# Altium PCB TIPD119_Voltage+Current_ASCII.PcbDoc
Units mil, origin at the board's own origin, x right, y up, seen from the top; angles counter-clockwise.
Board outline 2500 x 2500 mil, 4 copper layers (Top Layer, Mid-Layer 1, Mid-Layer 2, Bottom Layer); 44 components, 24 nets, 146 pads, 95 vias.
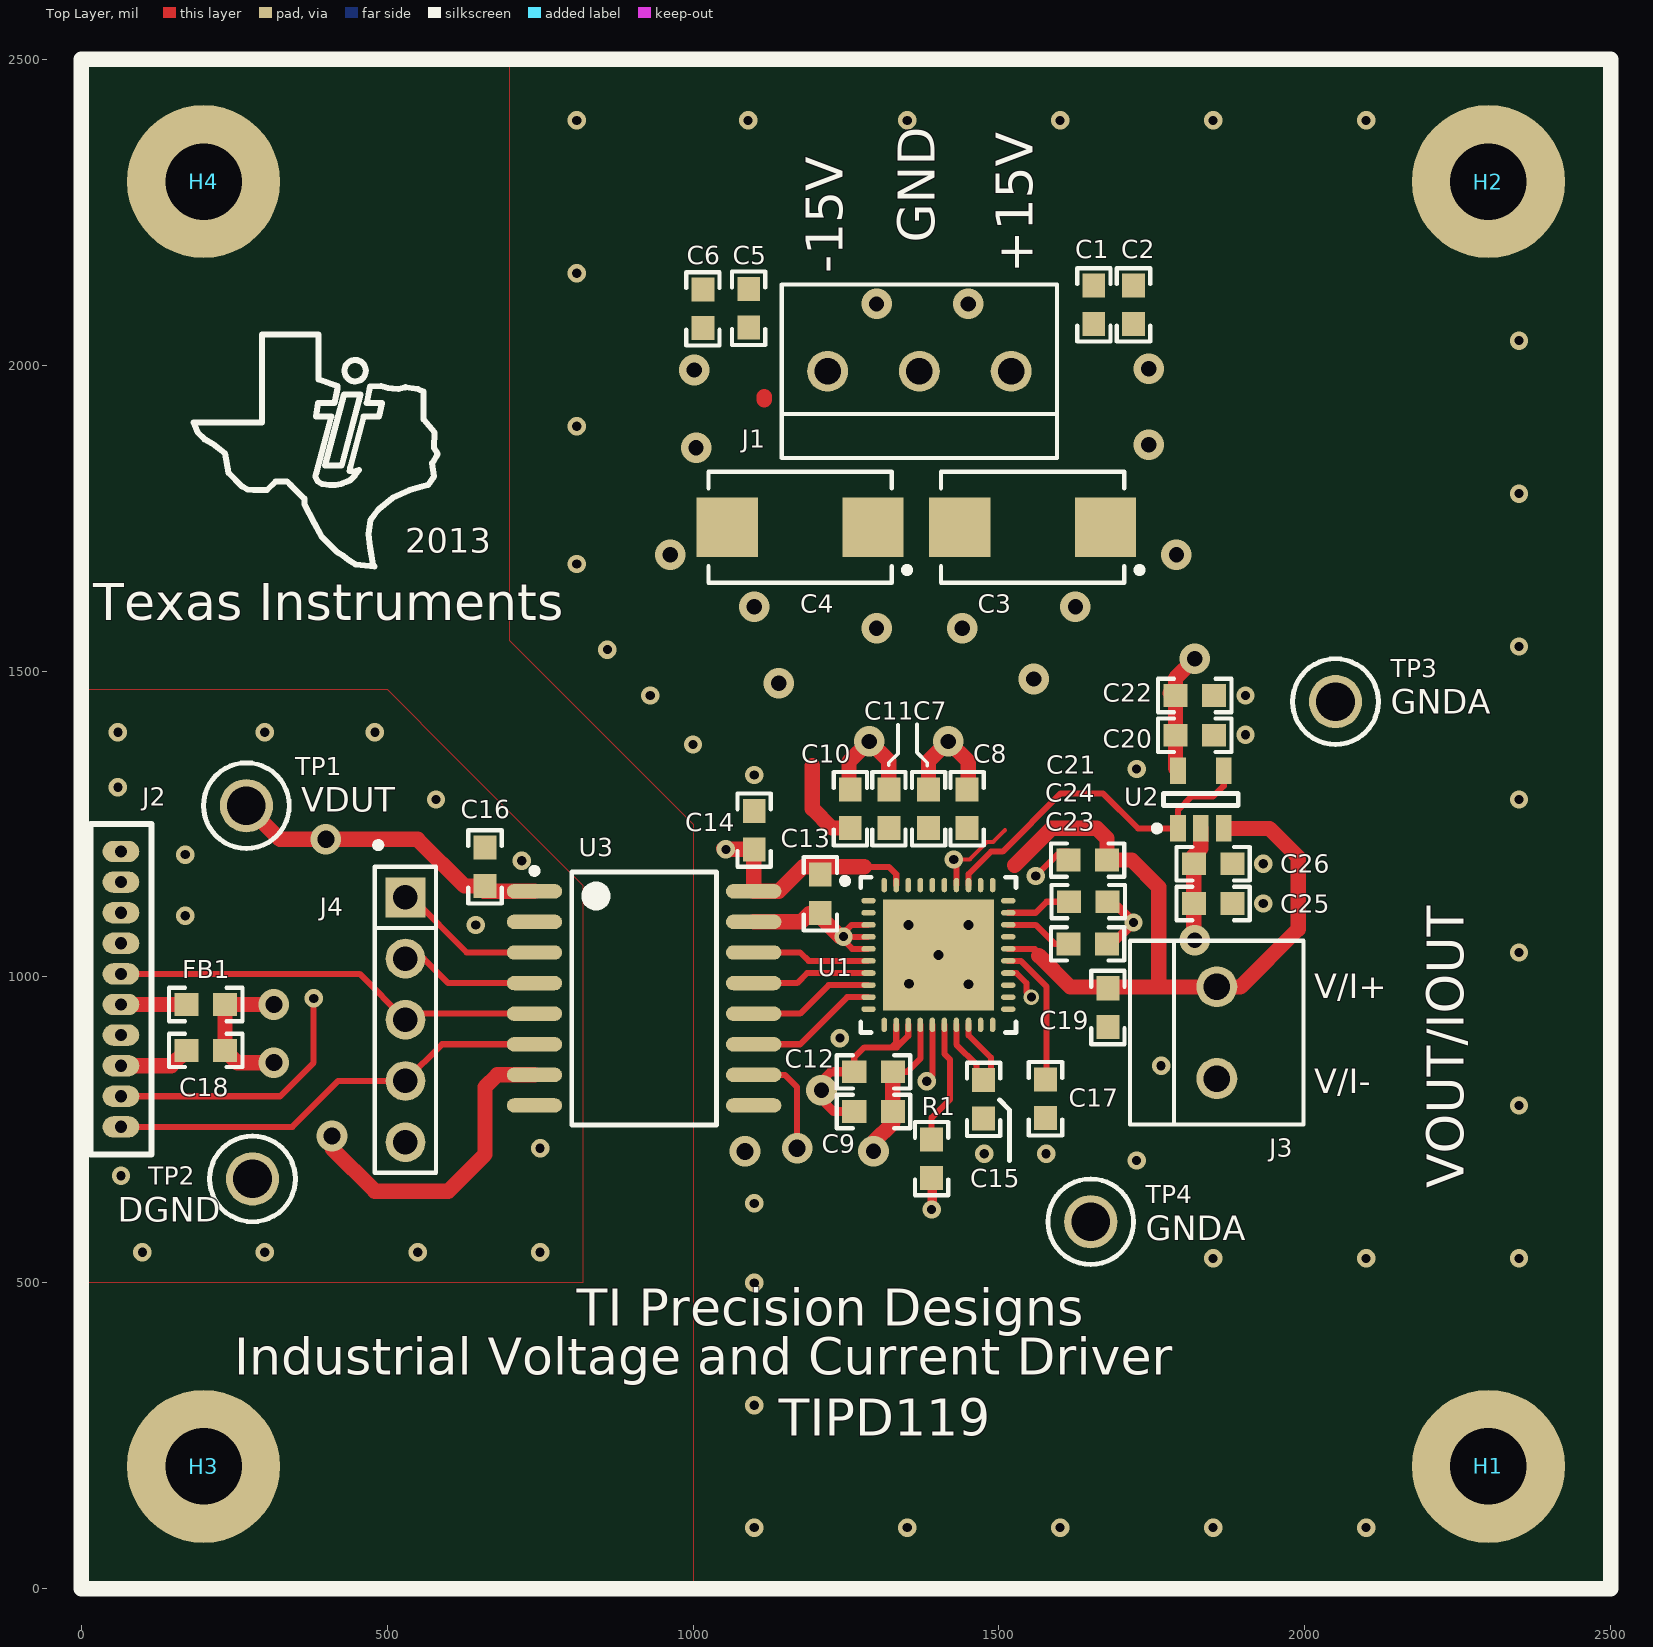
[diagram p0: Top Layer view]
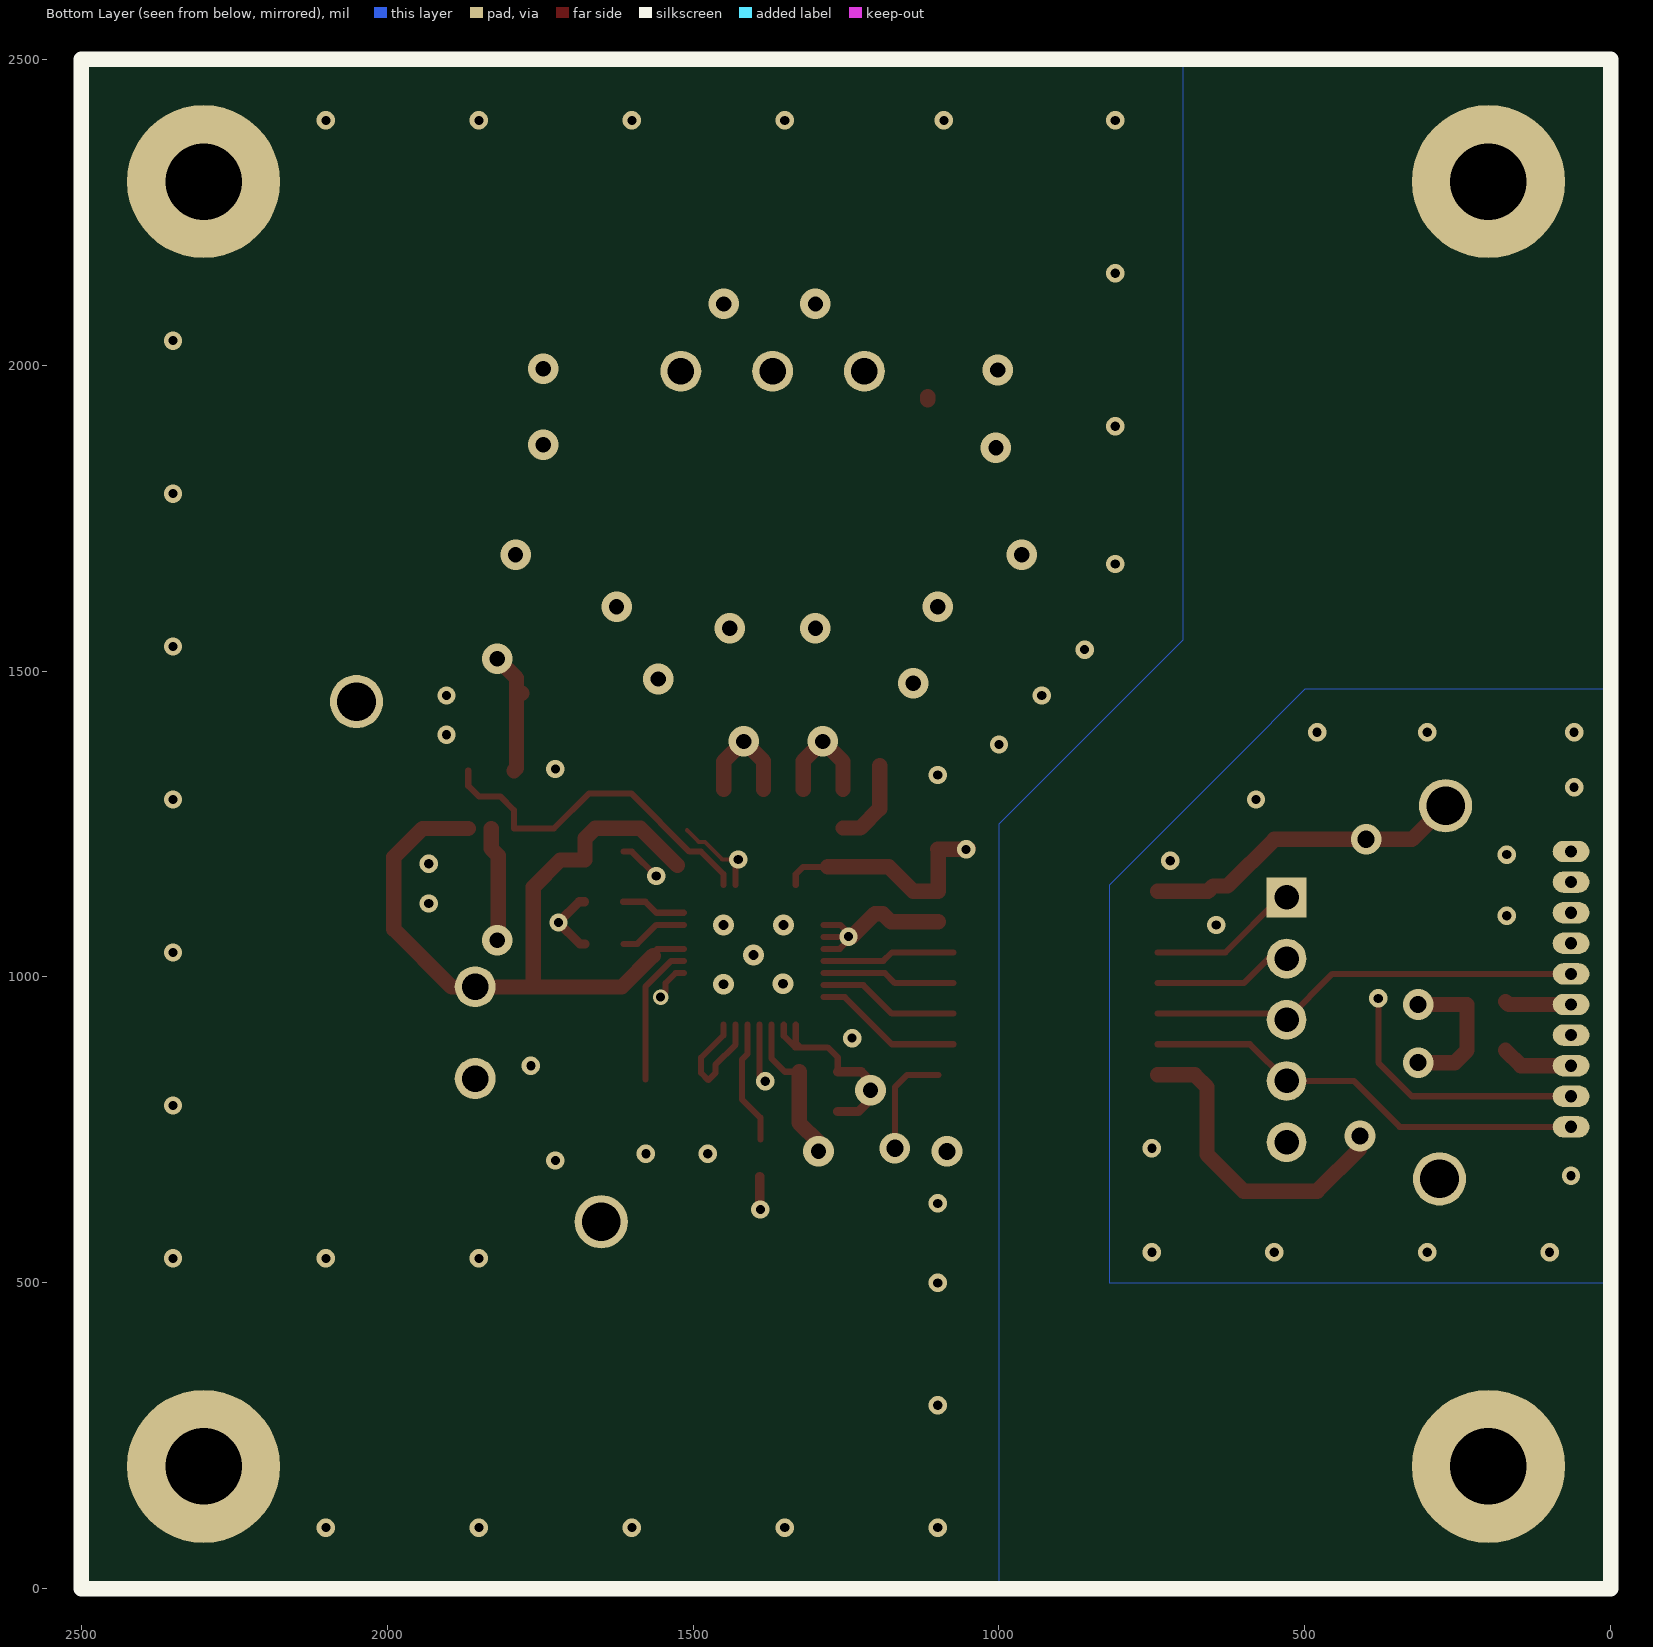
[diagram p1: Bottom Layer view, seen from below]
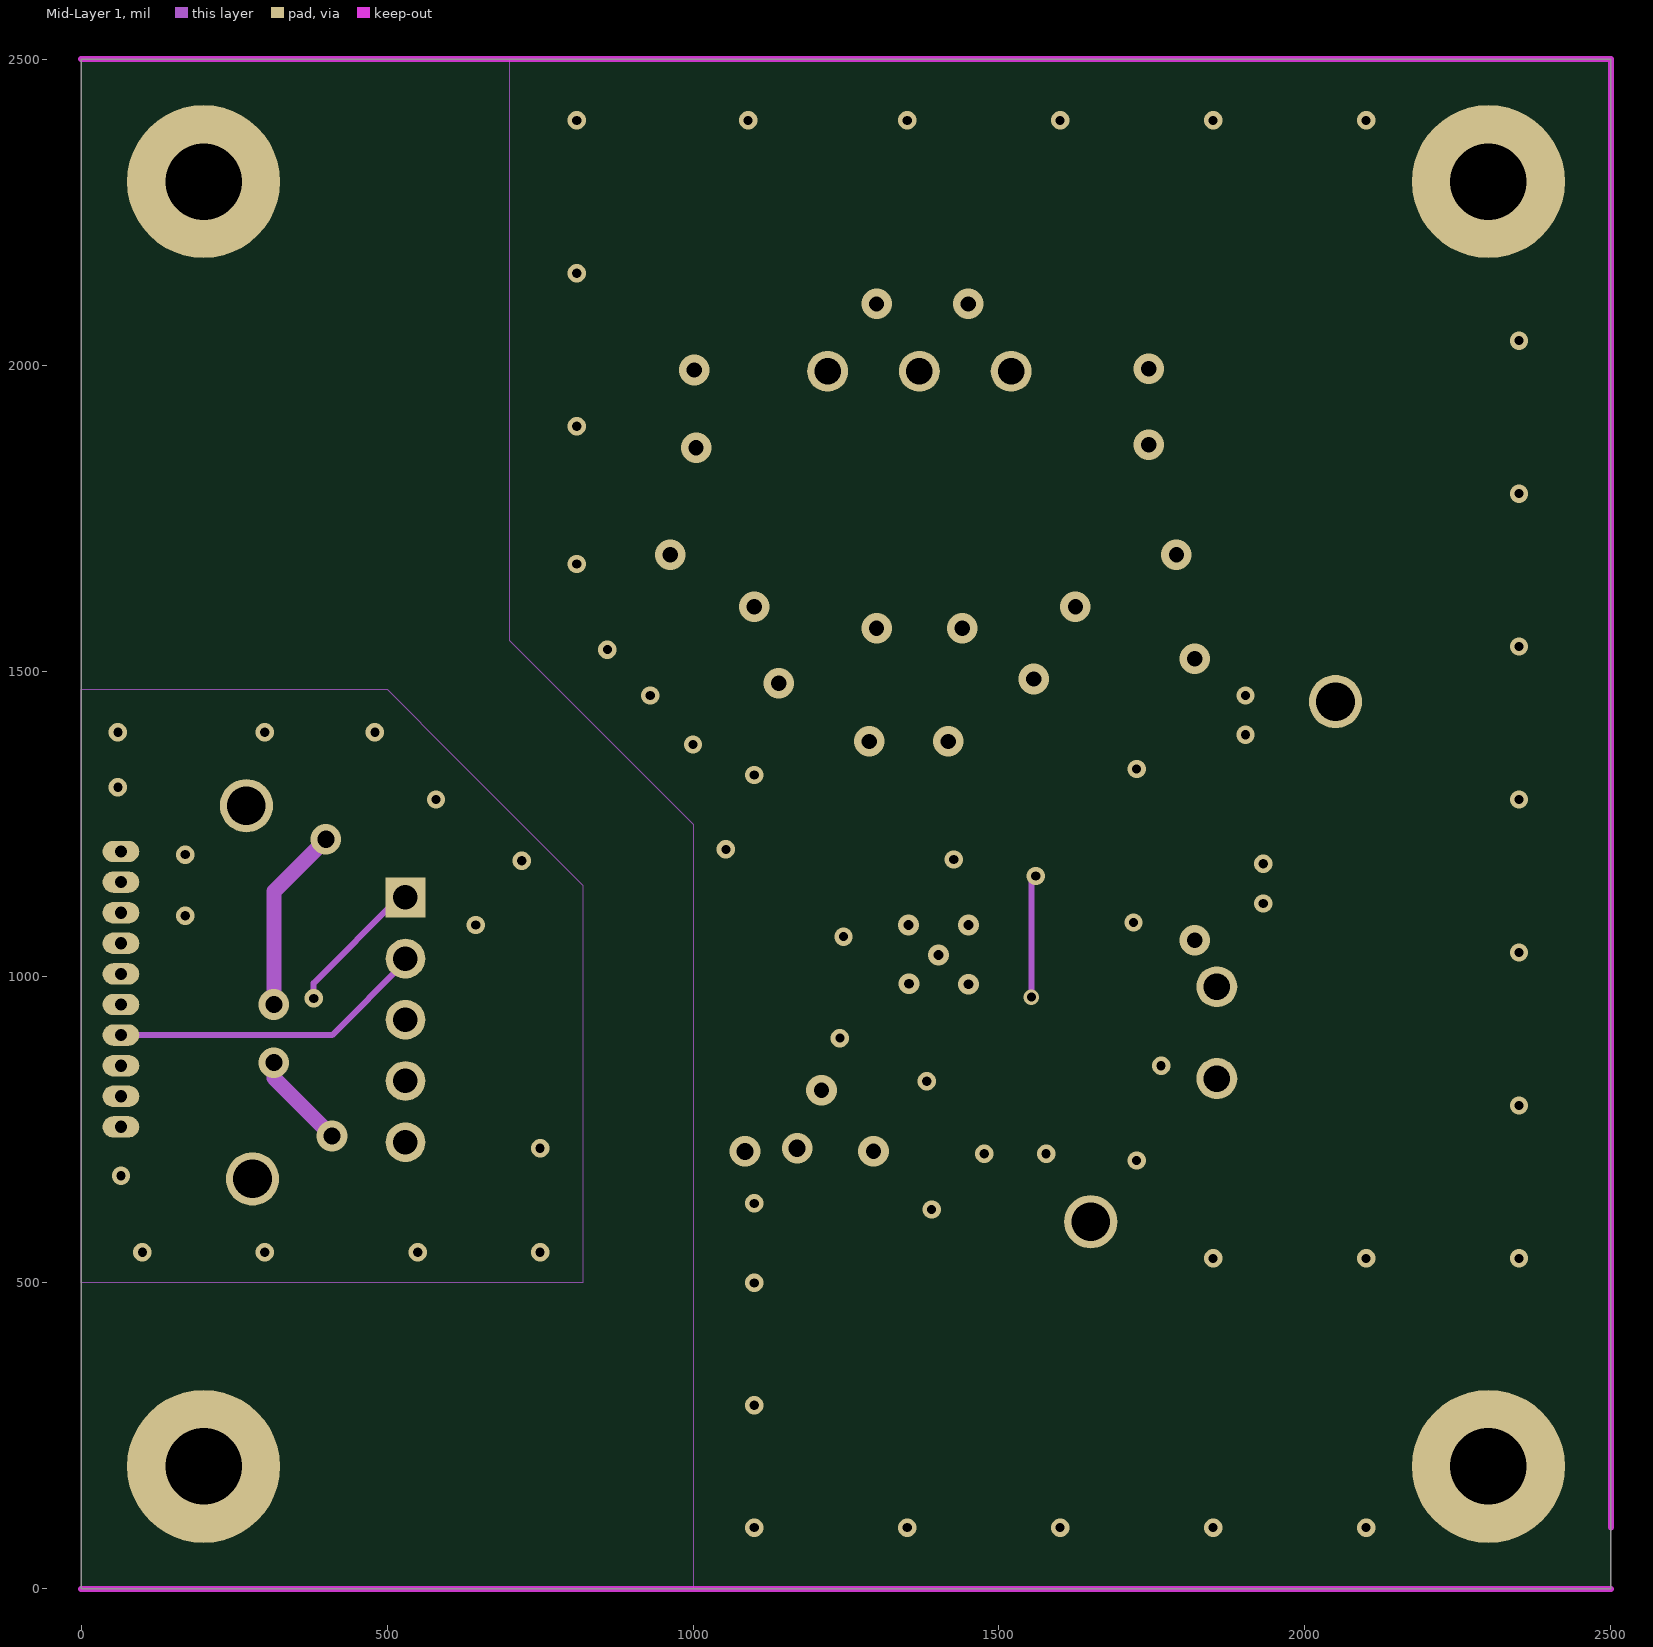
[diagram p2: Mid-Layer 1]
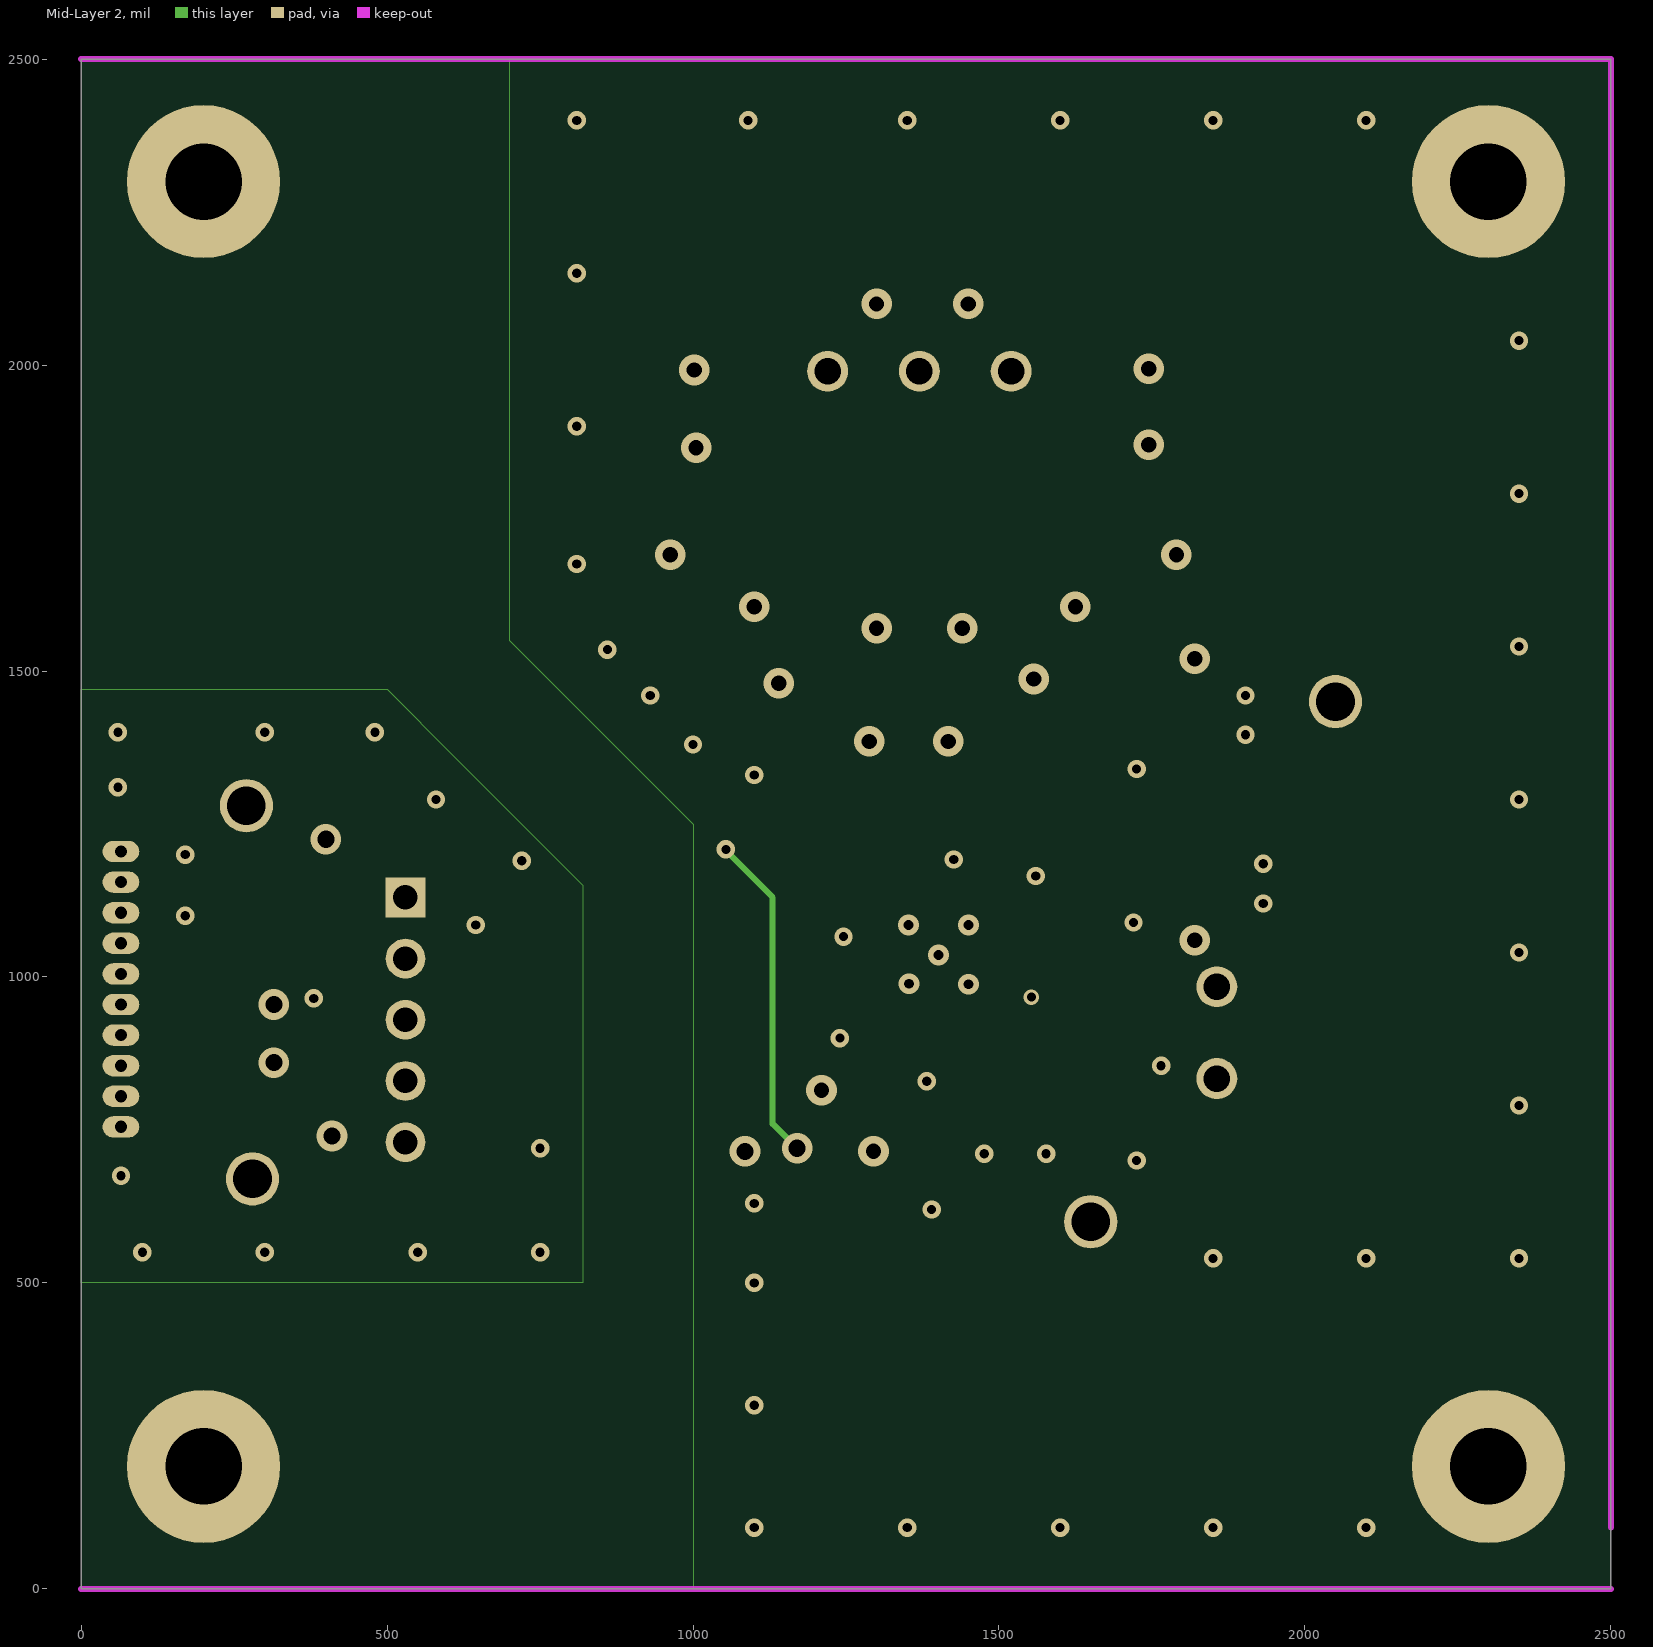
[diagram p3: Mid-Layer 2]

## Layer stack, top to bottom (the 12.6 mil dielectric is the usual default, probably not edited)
Top Layer: signal copper 1.4
Dielectric: core 12.6, FR-4, Dk 4.8
Mid-Layer 1: signal copper 1.4
Dielectric: prepreg 12.6, FR-4, Dk 4.8
Mid-Layer 2: signal copper 1.4
Dielectric: core 12.6, FR-4, Dk 4.8
Bottom Layer: signal copper 1.4

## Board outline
0,0 2500,0 2500,2500 0,2500

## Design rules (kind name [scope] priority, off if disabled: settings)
AssemblyTestPointUsage [All] p0: scope1count=1 scope1_0_kind=Board scope1_0_value=Board scope2count=1 scope2_0_kind=Board scope2_0_value=Board commentlength=0
AssemblyTestpoint [All] p0: scope1count=1 scope1_0_kind=Board scope1_0_value=Board scope2count=1 scope2_0_kind=Board scope2_0_value=Board commentlength=0
Clearance [All] p0: scope1count=1 scope1_0_kind=Board scope1_0_value=Board scope2count=1 scope2_0_kind=Board scope2_0_value=Board commentlength=0 gap=7
Clearance [All] p1: gap=7
ComponentClearance [All] p0: scope1count=1 scope1_0_kind=Board scope1_0_value=Board scope2count=1 scope2_0_kind=Board scope2_0_value=Board commentlength=0 gap=10 collisioncheckmode=3
DiffPairsRouting [All] p0: scope1count=1 scope1_0_kind=Board scope1_0_value=Board scope2count=1 scope2_0_kind=Board scope2_0_value=Board commentlength=0
FabricationTestPointUsage [All] p0: scope1count=1 scope1_0_kind=Board scope1_0_value=Board scope2count=1 scope2_0_kind=Board scope2_0_value=Board commentlength=0 valid=0 allowmultiple=FALSE
FabricationTestpoint [All] p0: scope1count=1 scope1_0_kind=Board scope1_0_value=Board scope2count=1 scope2_0_kind=Board scope2_0_value=Board commentlength=0 side=3 testpointundercomponent=TRUE minsize=40 maxsize=100 preferedsize=60 minholesize=0 maxholesize=40 preferedholesize=32 testpointgrid=1
FanoutControl Fanout_Default [All] p0: scope1count=1 scope1_0_kind=Board scope1_0_value=Board scope2count=1 scope2_0_kind=Board scope2_0_value=Board commentlength=30 // Fanout_Default (Default Rule)
FanoutControl Fanout_Small [All] p0 off: scope1count=1 scope1_0_kind=Board scope1_0_value=Board scope2count=1 scope2_0_kind=Board scope2_0_value=Board commentlength=84 // Protel DXP Scope 1 Expression Was: (CompPinCount < 5)   Fanout_Small (Default Rule)
FanoutControl Fanout_SOIC [All] p0 off: scope1count=1 scope1_0_kind=Board scope1_0_value=Board scope2count=1 scope2_0_kind=Board scope2_0_value=Board commentlength=71 // Protel DXP Scope 1 Expression Was: IsSOIC   Fanout_SOIC (Default Rule)
FanoutControl Fanout_LCC [All] p0 off: scope1count=1 scope1_0_kind=Board scope1_0_value=Board scope2count=1 scope2_0_kind=Board scope2_0_value=Board commentlength=69 // Protel DXP Scope 1 Expression Was: IsLCC   Fanout_LCC (Default Rule)
FanoutControl Fanout_BGA [All] p0 off: scope1count=1 scope1_0_kind=Board scope1_0_value=Board scope2count=1 scope2_0_kind=Board scope2_0_value=Board commentlength=69 // Protel DXP Scope 1 Expression Was: IsBGA   Fanout_BGA (Default Rule)
Height [All] p0: scope1count=1 scope1_0_kind=Board scope1_0_value=Board scope2count=1 scope2_0_kind=Board scope2_0_value=Board commentlength=0
HoleSize [All] p0: scope1count=1 scope1_0_kind=Board scope1_0_value=Board scope2count=1 scope2_0_kind=Board scope2_0_value=Board commentlength=0 absolutevalues=TRUE maxlimit=146 minlimit=1 maxpercent=80.000 minpercent=20.000
HoleSize [All] p1: absolutevalues=TRUE maxlimit=146 minlimit=1 maxpercent=80.000 minpercent=20.000
HoleToHoleClearance [All] p0: scope1count=1 scope1_0_kind=Board scope1_0_value=Board scope2count=1 scope2_0_kind=Board scope2_0_value=Board commentlength=0
HoleToHoleClearance [All] p1: gap=0 allowstackedmicrovias=TRUE
LayerPairs [All] p0: scope1count=1 scope1_0_kind=Board scope1_0_value=Board scope2count=1 scope2_0_kind=Board scope2_0_value=Board commentlength=0 enforce=TRUE
MinimumSolderMaskSliver [All] p0: scope1count=1 scope1_0_kind=Board scope1_0_value=Board scope2count=1 scope2_0_kind=Board scope2_0_value=Board commentlength=0
MinimumSolderMaskSliver [All] p1: minsoldermaskwidth=0
NetAntennae [All] p0: scope1count=1 scope1_0_kind=Board scope1_0_value=Board scope2count=1 scope2_0_kind=Board scope2_0_value=Board commentlength=0
PasteMaskExpansion [All] p0: scope1count=1 scope1_0_kind=Board scope1_0_value=Board scope2count=1 scope2_0_kind=Board scope2_0_value=Board commentlength=0 expansion=0
PlaneClearance [All] p0: scope1count=1 scope1_0_kind=Board scope1_0_value=Board scope2count=1 scope2_0_kind=Board scope2_0_value=Board commentlength=0 clearance=20
PlaneConnect [All] p0: scope1count=1 scope1_0_kind=Board scope1_0_value=Board scope2count=1 scope2_0_kind=Board scope2_0_value=Board commentlength=0 planeconnectstyle=Relief reliefexpansion=20 reliefentries=4 reliefconductorwidth=10 reliefairgap=10
PolygonConnect PolygonConnect_1 [All] p0 off: scope1count=1 scope1_0_kind=Board scope1_0_value=Board scope2count=1 scope2_0_kind=Board scope2_0_value=Board commentlength=75 connectstyle=Relief reliefconductorwidth=20 reliefentries=4 polygonreliefangle="90 Angle" // Protel DXP Scope 1 Expression Was: (InComponentClass('All Components'))
PolygonConnect [All] p0: scope1count=1 scope1_0_kind=Board scope1_0_value=Board scope2count=1 scope2_0_kind=Board scope2_0_value=Board commentlength=0 connectstyle=Direct reliefconductorwidth=20 reliefentries=4 polygonreliefangle="90 Angle"
PolygonConnect PolygonConnect_1 [(InComponentClass('All Components'))] p1: connectstyle=Relief reliefconductorwidth=20 reliefentries=4 polygonreliefangle="90 Angle" airgapwidth=10
PolygonConnect [All] p2: connectstyle=Direct reliefconductorwidth=20 reliefentries=4 polygonreliefangle="90 Angle" airgapwidth=10
RoutingCorners [All] p0: scope1count=1 scope1_0_kind=Board scope1_0_value=Board scope2count=1 scope2_0_kind=Board scope2_0_value=Board commentlength=0 cornerstyle=45-Degree minsetback=100 maxsetback=100
RoutingLayers [All] p0: scope1count=1 scope1_0_kind=Board scope1_0_value=Board scope2count=1 scope2_0_kind=Board scope2_0_value=Board commentlength=0 top layer=Automatic mid layer 1=Automatic mid layer 2=Automatic bottom layer=Automatic
RoutingPriority [All] p0: scope1count=1 scope1_0_kind=Board scope1_0_value=Board scope2count=1 scope2_0_kind=Board scope2_0_value=Board commentlength=0
RoutingTopology [All] p0: scope1count=1 scope1_0_kind=Board scope1_0_value=Board scope2count=1 scope2_0_kind=Board scope2_0_value=Board commentlength=0 topology=Shortest
RoutingVias [All] p0: scope1count=1 scope1_0_kind=Board scope1_0_value=Board scope2count=1 scope2_0_kind=Board scope2_0_value=Board commentlength=0 holewidth=15 width=30 viastyle="Through Hole" minholewidth=15 minwidth=30 maxholewidth=28 maxwidth=50
RoutingVias [All] p1: holewidth=15 width=30 viastyle="Through Hole" minholewidth=15 minwidth=30 maxholewidth=28 maxwidth=50
ShortCircuit [All] p0: scope1count=1 scope1_0_kind=Board scope1_0_value=Board scope2count=1 scope2_0_kind=Board scope2_0_value=Board commentlength=0 allowed=FALSE
SilkToSilkClearance [All] p0 off: scope1count=1 scope1_0_kind=Board scope1_0_value=Board scope2count=1 scope2_0_kind=Board scope2_0_value=Board commentlength=0
SilkToSilkClearance [All] p1 off: silktosilkclearance=10
SilkscreenOverComponentPads [All] p0 off: scope1count=1 scope1_0_kind=Board scope1_0_value=Board scope2count=1 scope2_0_kind=Board scope2_0_value=Board commentlength=0
SilkscreenOverComponentPads [All] p1 off: minsilkscreentomaskgap=10
SolderMaskExpansion [All] p0: scope1count=1 scope1_0_kind=Board scope1_0_value=Board scope2count=1 scope2_0_kind=Board scope2_0_value=Board commentlength=0 expansion=4
SolderMaskExpansion [All] p1: expansion=4
UnRoutedNet [All] p0: scope1count=1 scope1_0_kind=Board scope1_0_value=Board scope2count=1 scope2_0_kind=Board scope2_0_value=Board commentlength=0
Width [All] p0: scope1count=1 scope1_0_kind=Board scope1_0_value=Board scope2count=1 scope2_0_kind=Board scope2_0_value=Board commentlength=0 maxlimit=200 minlimit=7 preferedwidth=10
Width [All] p1: maxlimit=200 minlimit=7 preferedwidth=10
23 further rules are at their usual default settings.

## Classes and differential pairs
component class Header: J4

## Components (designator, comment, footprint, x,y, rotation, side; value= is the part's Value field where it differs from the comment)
C1 "GRM188R71H104KA93D" 0603 1655,2098.5 r270 top
C2 "06035A101JAT2A" 0603 1720,2098.5 r90 top
C3 "293D106X9050E2TE3" 7343-43 1555,1735 r180 top
C4 "293D106X9050E2TE3" 7343-43 1175,1735 r180 top
C5 "GRM188R71H104KA93D" 0603 1091,2093 r90 top
C6 "06035A101JAT2A" 0603 1016,2092 r270 top
C7 "GRM188R71H104KA93D" 0603 1385,1275 r90 top
C8 "06035A101JAT2A" 0603 1448,1275 r90 top
C9 "06035A101JAT2A" 0603 1295,780 r0 top
C10 "GRM188R71H104KA93D" 0603 1257,1275 r270 top
C11 "06035A101JAT2A" 0603 1320,1275 r270 top
C12 "GRM188R71H104KA93D" 0603 1295,845 r0 top
C13 "GRM188R71H104KA93D" 0603 1208,1136 r270 top
C14 "GRM188R71H104KA93D" 0603 1100,1240 r90 top
C15 "GRM188R71H104KA93D" 0603 1475,800 r270 top
C16 "GRM188R71H104KA93D" 0603 660,1180 r90 top
C17 "C1608X7R1H223K" 0603 1576,801 r270 top
C18 "GRM188R71H104KA93D" 0603 203.5,880 r180 top
C19 "DNI" 0603 1678,950 r270 top
C20 "GRM188R71H104KA93D" 0603 1820,1395 r0 top
C21 "DNI" 0603 1645,1191 r180 top
C22 "06035A101JAT2A" 0603 1820,1460 r0 top
C23 "DNI" 0603 1645,1054 r180 top
C24 "DNI" 0603 1646,1123 r180 top
C25 "GRM188R71H104KA93D" 0603 1850,1120 r0 top
C26 "06035A101JAT2A" 0603 1850,1185 r0 top
FB1 "BLM18HG601SN1D" 0603 203.5,955 r0 top
H1 "NA" "Mounting Hole"#1 2800,200 r0 top
H2 "NA" "Mounting Hole"#2 2800,2800 r0 top
H3 "NA" "Mounting Hole"#3 200,200 r0 top
H4 "NA" "Mounting Hole"#4 191,2785 r0 top
J1 "ED555/3DS" ED555/3DS 1220,1990 r0 top
J2 "851-43-050-20-001000" 851-43-010-20-001000 65,980 r0 top
J3 "V+I" ED555/2DS 1856,984 r270 top
J4 "TSW-105-07-G-S" TSW-105-07-G-S 530,930 r270 top
R1 "RG1608P-153-B-T5" 0603 1390,702.99 r90 top
TI1 "Texas Instruments logo" "TI LOGO" 6680,5973 r0 top
TP1 "5005" Keystone5005 270,1280 r90 top
TP2 "5006" Keystone5006 280,670 r90 top
TP3 "5006" Keystone5006 2050,1450 r90 top
TP4 "5006" Keystone5006 1650,600 r90 top
U1 "DAC8760RHA" RHA0040C 1401,1036 r0 top
U2 "LMV721M5" MF05A_N 1830,1290 r90 top
U3 "ISO7641FCDW" M16B_N 920,965 r0 top

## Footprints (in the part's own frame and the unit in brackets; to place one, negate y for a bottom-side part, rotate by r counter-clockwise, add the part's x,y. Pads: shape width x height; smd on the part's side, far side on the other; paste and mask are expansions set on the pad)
0603 [mm] "0603 from SM-752 data"
  rect 1x0.95 smd: 1(-0.8,0) 2(0.8,0)
  silkscreen extent -1.52,-0.69 1.52,0.69
851-43-010-20-001000 [mil] "Female 10 Pin connector for SM-USB-DIG"
  oval 60x35 hole 20: 1(0,225) 2(0,175) 3(0,125) 4(0,75) 5(0,25) 6(0,-25) 7(0,-75) 8(0,-125) 9(0,-175) 10(0,-225)
  silkscreen extent -50,-270 50,270
7343-43 [mm] "Medium density IPC based on Kemet T495 series"
  rect 2.55x2.45 smd: 1(-3.025,0) 2(3.025,0)
  silkscreen extent -4.56,-2.3 3.8,2.3
ED555/2DS [mm] "TERMINAL BLOCK 3.5MM 2POS PCB"
  round 1.7 hole 1.1: 1(0,0) 2(3.81,0)
  silkscreen extent -1.91,-3.6 5.72,3.6
ED555/3DS [mm] "TERMINAL BLOCK 3.5MM 3POS PCB"
  round 1.7 hole 1.1: 1(0,0) 2(3.81,0) 3(7.62,0)
  silkscreen extent -1.91,-3.6 9.53,3.6
Keystone5005 [mil] "Keystone Compact loops"
  round 87 hole 63: 1(0,0)
  silkscreen extent -70,-70 70,70
Keystone5006 [mil] "Keystone Compact loops"
  round 87 hole 63: 1(0,0)
  silkscreen extent -70,-70 70,70
M16B_N [mm] "SOIC, 16-Leads, Body 10.3x7.5mm, Pitch 1.27mm, IPC Medium Density"
  oval 2.3x0.6 smd: 1(-4.55,4.445) 2(-4.55,3.175) 3(-4.55,1.905) 4(-4.55,0.635) 5(-4.55,-0.635) 6(-4.55,-1.905) 7(-4.55,-3.175) 8(-4.55,-4.445) 9(4.55,-4.445) 10(4.55,-3.175) 11(4.55,-1.905) 12(4.55,-0.635) 13(4.55,0.635) 14(4.55,1.905) 15(4.55,3.175) 16(4.55,4.445)
  silkscreen extent -4.67,-5.25 3,5.42
MF05A_N [mm] "SOT23, 5-Leads, Body 2.9x1.6mm, Pitch 0.95mm, Lead Span 2.8mm, IPC Medium Density"
  rect 1.1x0.65 smd: 1(-1.2,0.95) 2(-1.2,0) 3(-1.2,-0.95) 4(1.2,-0.95) 5(1.2,0.95)
  silkscreen extent -1.32,-1.55 0.25,1.95
"Mounting Hole"#1 [mil]
  round 250 hole 125: 1(-500,0)
"Mounting Hole"#2 [mil]
  round 250 hole 125: 1(-500,-500)
"Mounting Hole"#3 [mil]
  round 250 hole 125: 1(0,0)
"Mounting Hole"#4 [mil]
  round 250 hole 125: 1(9,-485)
RHA0040C [mm] "QFN, 40-Leads, Body 6x6mm, Pitch 0.5mm, Thermal Pad 4.6 x 4.6mm, TI Recommended"
  oval 0.6x0.23 smd mask+0.07: 1(-2.9,2.25) 2(-2.9,1.75) 3(-2.9,1.25) 4(-2.9,0.75) 5(-2.9,0.25) 6(-2.9,-0.25) 7(-2.9,-0.75) 8(-2.9,-1.25) 9(-2.9,-1.75) 10(-2.9,-2.25) 21(2.9,-2.25) 22(2.9,-1.75) 23(2.9,-1.25) 24(2.9,-0.75) 25(2.9,-0.25) 26(2.9,0.25) 27(2.9,0.75) 28(2.9,1.25) 29(2.9,1.75) 30(2.9,2.25)
  oval 0.23x0.6 smd mask+0.07: 11(-2.25,-2.9) 12(-1.75,-2.9) 13(-1.25,-2.9) 14(-0.75,-2.9) 15(-0.25,-2.9) 16(0.25,-2.9) 17(0.75,-2.9) 18(1.25,-2.9) 19(1.75,-2.9) 20(2.25,-2.9) 31(2.25,2.9) 32(1.75,2.9) 33(1.25,2.9) 34(0.75,2.9) 35(0.25,2.9) 36(-0.25,2.9) 37(-0.75,2.9) 38(-1.25,2.9) 39(-1.75,2.9) 40(-2.25,2.9)
  rect 4.6x4.6 smd paste-2.5 mask+0.07: 41(0,0)
  silkscreen extent -4,-3.22 3.22,3.22
"TI LOGO" [mil] "TI BUG"
  silkscreen extent -6496,-4302 -6097,-3923
TSW-105-07-G-S [mm] "Samtec 100mil, 1x5, 230 mil above insulator"
  rect 1.65x1.65 hole 1.016 mask+0: 1(-5.08,0)
  round 1.65 hole 1.016 mask+0: 2(-2.54,0) 3(0,0) 4(2.54,0) 5(5.08,0)
  silkscreen extent -7.37,-1.27 6.35,1.27

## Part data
C1 C5 C7 C10 C12 C13 C14 C15 C16 C18 C20 C25: "CAP, CERM, 0.1uF, 50V, +/-10%, X7R, 0603"
C2 C6 C8 C9 C11 C22 C26: "CAP, CERM, 100pF, 50V, +/-5%, C0G/NP0, 0603"
C3 C4: "CAP, TANT, 10uF, 50V, +/-10%, 0.8 ohm, 7343-43 SMD"
C17: "CAP, CERM, 0.022uF, 50V, +/-10%, X7R, 0603"
C19 C21 C23 C24: library part GRM188R72A102KA01D, "CAP, CERM, 1000pF, 100V, +/-10%, X7R, 0603"
FB1: library part Ferrite_Bead, "FERRITE CHIP 600 OHM 200MA 0603"
H1 H2 H3 H4: library part "Mounting Hole", "Mounting Hole"
J1: library part 1715734, "TERMINAL BLOCK 3.5MM 3POS PCB"
J2: library part SM-USB-DIG-CONN, "CONN SOCKET 50PIN .050 R/A SNGL"
J3: library part 1727010, "TERMINAL BLOCK 3.5MM 2POS PCB"
J4: "Header, TH, 100mil, 5x1, Gold plated, 230 mil above insulator"
R1: "RES, 15.0k ohm, 0.1%, 0.1W, 0603"
TI1: library part "TI LOGO", "TI BUG"
TP1: "Test Point, Compact, Red, TH"
TP2 TP3 TP4: "Test Point, Compact, Black, TH"
U1: "Single-Channel, 16-Bit Programmable Current Output and Voltage Output DIGITAL-TO-ANALOG CONVERTER for 4-mA to 20-mA Current Loop Applications, RHA0040C"
U2: "10MHz Low Noise, Low Voltage Op Amp"
U3: library part ISO7241, "ISOLATOR DGTL 25MBPS 4CH 16SOIC"

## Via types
v1: diameter 30, hole 15, Top Layer to Bottom Layer, 63 vias
v2: diameter 50, hole 25, Top Layer to Bottom Layer, 20 vias
v3: diameter 50, hole 28, Top Layer to Bottom Layer, 6 vias
v4: diameter 34, hole 16, Top Layer to Bottom Layer, 5 vias
v5: diameter 25, hole 15, Top Layer to Bottom Layer, 1 vias

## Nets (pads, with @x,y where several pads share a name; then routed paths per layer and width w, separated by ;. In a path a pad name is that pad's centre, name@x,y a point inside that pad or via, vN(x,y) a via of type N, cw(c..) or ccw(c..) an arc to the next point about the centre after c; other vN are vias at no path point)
+15VA: C1.2 C2.1 C3.1 C7.1 C8.1 C20.1 C22.1 C23.1 C24.1 J1.3 U1.36 U2.5 | length 314.2
  Top Layer w15: C23.1 1685,1054 v1(1720,1089) 1686,1123 C24.1
  Top Layer w25: C22.1@1780,1463.5 C22.1@1781.5,1465 ; U2.5 1788.5,1341.34 C20.1 C22.1 1788.5,1488.5 v2(1820,1520)
  other v2: 1557,1487 1625,1605 1790,1690 1745,1870 1745,1994
-15VA: C4.2 C5.1 C6.2 C9.2 C10.2 C11.2 C12.2 C25.1 C26.1 J1.1 U1.14 U1.37 U1.41 U2.2 | length 588.7
  Top Layer w10: C12.2 1350,845 1371.47,866.47 U1.14
  Top Layer w25: 1116.39,1943.4 1116.39,1948.6 ; 1195,1345 1195,1275 1226.5,1243.5 C10.2@1255,1243.5 ; v2(1295,715) 1295,730 1326.5,761.5 C9.2 C12.2 ; v2(1820,1060) 1818.5,1061.5 C25.1 C26.1 1818.5,1198.5 1830,1210 U2.2
  other v2: 1140,1480 1100,1605 963,1690 1005,1865 1002,1992
  other v4: 1450,988 1353,989 1401,1036 1352,1085 1450,1085
\C\S_DAC: U1.6 U3.14 | length 218.4
  Top Layer w10: U3.14@1074.13,1040 1175,1040 1188.84,1026.16 U1.6
\C\S_DIG: J2.9 J4.1 U3.3 | length 923.9
  Top Layer w10: J2.9 325,805 380,860 v1(380,965) ; J4.1 540,1130 630,1040 U3.3
  Mid-Layer 1 w10: v1(380,965) 380,990 520,1130 J4.1
DGND: C16.2 C18.2 J2.8 J4.5 TP2.1 U3.2 U3.8 | length 117.4
  Top Layer w25: J2.8 147.01,855 C18.2
  other v1: 100,550 300,550 550,550 750,550 65,675 750,720 645,1085 170,1100 720,1190 170,1200 580,1290 60,1310 60,1400 300,1400 480,1400
GNDA: C1.1 C2.2 C3.2 C4.1 C5.2 C6.1 C7.2 C8.2 C9.1 C10.1 C11.1 C12.1 C13.2 C14.2 C15.2 C17.2 C19.2 C20.2 C22.2 C25.2 C26.2 J1.2 J3.2 R1.1 TP3.1 TP4.1 U1.3 U1.4 U1.5 U1.12 U1.13 U1.15 U1.34 U3.9 U3.15 | length 1357.7
  Top Layer w7: v1(1426,1192) 1432,1192 1452.08,1192 1480.58,1220.5 1490.5,1220.5 1510,1240
  Top Layer w10: v1(1246,1066) 1246,1072 1247,1073 v1@1240,1066 ; C12.1 1263.5,868.5 1280,885 1325,885 ; U1.5 1260.16,1045.84 v1@1240,1066 ; U1.4 1256.47,1065.53 1256,1066 v1@1240,1066 ; U1.3 1259.21,1085.21 v1@1240,1066 ; U1.12 1332.1,892.1 1325,885 ; U1.13 1351.79,903.76 1333.03,885 1325,885 ; v1@1376,823.5 v1(1382,829.5) 1391.16,838.66 U1.15 ; U1.34 1430.53,1190.53 v1@1432,1192
  Top Layer w15: C9.1 1230,780 1195,815 1225,845 C12.1 ; v1(1390,620) 1391,621 R1.1@1391,674
  Top Layer w25: U3.15 1176.5,1090 1190,1103.5 1202.5,1103.5 v1@1240,1066 ; C10.1@1255,1306.5 1255,1352 v2(1288,1385) 1320,1353 C11.1 ; C7.2 1385,1353 v2(1417,1385) 1450,1352 C8.2@1450,1306.5
  other v1: 1100,100 1350,100 1600,100 1850,100 2100,100 1100,300 1100,500 1850,540 2100,540 2350,540 1100,630 1725,700 1476,711 1577,711 2350,790 1765,855 1240,900 2350,1040 1932,1120 1932,1185 2350,1290 1100,1330 1725,1340 1000,1380 1903,1396 930,1460 1903,1460 860,1535 2350,1540 810,1675 2350,1790 810,1900 2350,2040 810,2150 810,2400 1090,2400 1350,2400 1600,2400 1850,2400 2100,2400
  other v2: 1210,815 1300,1570 1440,1570 1300,2100 1450,2100
  other v3: 1085,715
GPIO4: J2.2
MISO_DAC: U1.9 U3.11 | length 244.6
  Top Layer w10: U3.11@1074.13,890 1175,890 1252.1,967.1 U1.9
MISO_DIG: J2.10 J4.4 U3.6 | length 731.8
  Top Layer w10: J2.10 345,755 420,830 J4.4 590,890 U3.6
MOSI_DAC: U1.8 U3.12 | length 232.1
  Top Layer w10: U3.12@1074.13,940 1175,940 1221.79,986.79 U1.8
MOSI_DIG: J2.5 J4.3 U3.5 | length 711.1
  Top Layer w10: J2.5 455,1005 J4.3 540,940 U3.5
NetC13_1: C13.1 C14.1 U1.39 U3.10 U3.16 | length 1117
  Top Layer w10: U3.10 1150,840 1170,820 v3(1170,720) ; 1280,1180 1320,1180 1332.1,1167.9 U1.39
  Top Layer w25: v1@1050,1210 v1@1051.5,1208.5 ; v1(1053.62,1208.5) v1@1051.5,1208.5 ; 1280,1180 1180,1180 1140,1140 U3.16 1099.13,1207.64 C14.1 v1@1051.5,1208.5
  Mid-Layer 1 w10: v1@1050,1210 1051.5,1208.5 v1(1053.62,1208.5)
  Mid-Layer 2 w10: v1@1050,1210 1130,1130 1130,760 v3(1170,720)
NetC15_1: C15.1 U1.17 U1.18 | length 219.3
  Top Layer w10: U1.17 1430.53,889.47 1463.5,856.5 1463.5,843 C15.1 1487,843.5 1487,868 1450.21,904.79 U1.18
NetC17_1: C17.1 U1.25 | length 231.8
  Top Layer w10: U1.25 1535.84,1026.16 1578,984 C17.1@1578,832.5
NetC19_1: C19.1 C21.1 J3.1 U1.26 U1.32 U2.3 | length 1263.5
  Top Layer w10: U1.26 1559,1045.84
  Top Layer w25: 1525.5,1182.5 1586,1243 1660,1243 1676.5,1226.5 C21.1 1717,1191 1761,1147 1761,991.5 ; 1565.25,1034.75 1616.5,983.5 1894.5,983.5 1989,1078 1989,1196 1942.24,1242.76 U2.3
NetC21_2: C21.2 U1.24 | length 333.9
  Top Layer w10: U1.24 1528.53,1006.47 1545,990 1545,975 v5(1553,967) ; v1(1560,1165) 1600,1205 C21.2@1613.5,1205
  Mid-Layer 1 w10: v5(1553,967) 1553,1158 v1(1560,1165)
NetC23_2: C23.2 U1.28 | length 111.3
  Top Layer w10: U1.28 1559.79,1085.21 1591,1054 C23.2
NetC24_2: C24.2 U1.29 | length 106.8
  Top Layer w10: U1.29 1559.9,1104.9 1578,1123 C24.2
NetFB1_1: FB1.1 J2.6 | length 109.1
  Top Layer w25: J2.6 167.01,955 FB1.1@172.01,960
NetR1_2: R1.2 U1.16 | length 203.6
  Top Layer w10: R1.2 1390,770 1420,800 1420,865 1410.84,874.16 U1.16
NetU1_33: U1.33 U2.1 U2.4 | length 584.7
  Top Layer w10: U1.33 1450.21,1168.21 1487,1205 1506,1205 1601,1300 1670,1300 1727.24,1242.76 U2.1 1792.6,1272.6 1815,1295 1850,1295 1867.4,1312.4 U2.4
SCLK_DAC: U1.7 U3.13 | length 219.5
  Top Layer w10: U3.13@1074.13,990 1170,990 1186.47,1006.47 U1.7
SCLK_DIG: J2.7 J4.2 U3.4 | length 747.1
  Top Layer w10: J4.2 560,1030 600,990 U3.4
  Mid-Layer 1 w10: J2.7 410,905 530,1025 J4.2
VDUT: C16.1 C18.1 FB1.2 TP1.1 U3.1 U3.7 | length 1759.7
  Top Layer w25: TP1.1 325,1225 v3(400,1225) 550,1225 626.5,1148.5 650,1148.5 658.5,1140 U3.1 ; v3(315,860) 255,860 C18.1 FB1.2 v3(315,955) ; v3(410,740) 410,720 480,650 600,650 660,710 660,820 680,840 U3.7
  Mid-Layer 1 w25: v3(315,860) 315,835 v3(410,740) ; v3(315,955) 315,1140 v3(400,1225)
pads on no net: H1.1 H2.1 H3.1 H4.1 J2.1 J2.3 J2.4 U1.1 U1.2 U1.10 U1.11 U1.19 U1.20 U1.21 U1.22 U1.23 U1.27 U1.30 U1.31 U1.35 U1.38 U1.40

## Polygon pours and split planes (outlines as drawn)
GNDA on Top Layer "TOP_GND" (solid, remove dead copper, pour order 16): 700,2500 700,1550 1000,1250 1000,0 2500,0 2500,2500
DGND on Top Layer "Top Layer-No Net 2" (solid, remove dead copper, pour order 12): 0,1470 500,1470 610,1360 820,1150 820,856.78 820,500 0,500
GNDA on Bottom Layer "BOT_GND" (solid, remove dead copper, pour order 15): 700,2500 700,1550 1000,1250 1000,0 2500,0 2500,2500
DGND on Bottom Layer "Top Layer-No Net 2" (solid, remove dead copper, pour order 11): 0,1470 500,1470 610,1360 820,1150 820,856.78 820,500 0,500
+15VA on Mid-Layer 1 "MID1_V+" (solid, remove dead copper, pour order 14): 700,2500 700,1550 1000,1250 1000,0 2500,0 2500,2500
DGND on Mid-Layer 1 "Top Layer-No Net 2" (solid, remove dead copper, pour order 10): 0,1470 500,1470 610,1360 820,1150 820,856.78 820,500 0,500
-15VA on Mid-Layer 2 "MID2_V-" (solid, remove dead copper, pour order 13): 700,2500 700,1550 1000,1250 1000,0 2500,0 2500,2500
DGND on Mid-Layer 2 "Top Layer-No Net 2" (solid, remove dead copper, pour order 9): 0,1470 500,1470 610,1360 820,1150 820,856.78 820,500 0,500

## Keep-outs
Keep-Out Layer:
  lines w10: 0,0 2500,0 ; 0,2500 2500,2500 2500,100

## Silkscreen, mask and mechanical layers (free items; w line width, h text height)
Top Overlay:
  lines w6: 1320,1346 1320,1350 1335,1365 1335,1412 ; 1366,1413 1366,1367 1383,1350 1383,1345
  lines w8: 1501,799 1517,783 1517,700
  lines w25: 0,0 0,2500 2500,2500 2500,0 0,0
  text "GND" at 1395,2200 h60 r90
  text "-15V" at 1245,2150 h60 r90
  text "+15V" at 1555,2150 h60 r90
  text "2013" at 530,1693 h40
  text "Texas Instruments" at 20,1583 h60
  text "GNDA" at 2140,1430 h40
  text "VDUT" at 360,1270 h40
  text "V/I+" at 2015,965 h40
  text "V/I-" at 2015,810 h40
  text "VOUT/IOUT" at 2260,655 h60 r90
  text "DGND" at 60,600 h40
  text "GNDA" at 1740,570 h40
  text "TI Precision Designs" at 810,430 h60
  text "Industrial Voltage and Current Driver" at 250,350 h60
  text "TIPD119" at 1140,250 h60
Bottom Overlay:
  the board outline again, w25
Top Solder:
  the board outline again, w25
Bottom Solder:
  the board outline again, w25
